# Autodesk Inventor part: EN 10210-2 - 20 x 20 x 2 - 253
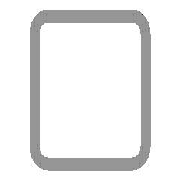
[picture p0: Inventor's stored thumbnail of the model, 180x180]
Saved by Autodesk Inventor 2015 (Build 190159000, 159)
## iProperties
Created: 2014-02
Part Number: EN 10210-2 - 20 x 20 x 2 - 253
Material: Steel, Mild
Description: Tube
Document SubType Name: Modeling
Standard: DIN
Designer: TREINA6
Standard Revision: 1997
Standards Organization: DIN
Language: en-US
Size Designation: 20 x 20 x 2
Categories: <MemberInstance><Categories><Category DisplayName="Structural Shapes" InternalName="089c4875-fa83-4c05-b084-43b9cc11f5ed" Mnemonic="GRDR"><CategoryParameter Dis
Stock Number: 20 x 20 x 2
Density: 7.85 g/cm^3
Appearance: Semi-Polished
_CCFamilyMember: 1
_CCFamilyDisplayName: DIN EN 10210-2 (Square) - Tube
_FrameMemberDoc: Frame Member File
_Version: 15.0.0
_GetPNFromCC: 1
IsCustomPart: 1
Author: TREINA6
G_L: 253,000 mm
G_W: 20,000 mm
G_H: 20,000 mm
+92CAF834-4A3A-427E-AD43-0E28CC12F767+CUTDETAIL1: Miter 45,00 deg
+C6974BCF-1B59-4DE7-8265-DB1344D5870A+CUTDETAIL2: Miter 45,00 deg
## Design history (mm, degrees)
node "Start plane"
node "End plane"
sketch "Sketch"
  geometry: L1 (-10, -7)-(-10, 7); L2 (-7, 10)-(7, 10); L3 (10, 7)-(10, -7); L4 (7, -10)-(-7, -10); L5 (-7, 8)-(7, 8); L6 (8, 7)-(8, -7); L7 (7, -8)-(-7, -8); L8 (-8, -7)-(-8, 7); L9 (0, 14.87)-(0, -14.87) reference; L10 (-14.87, 0)-(14.87, 0) reference; A1 r 3 centre (-7, -7) between (-10, -7) and (-7, -10); A2 r 3 centre (-7, 7) between (-7, 10) and (-10, 7); A3 r 3 centre (7, 7) between (10, 7) and (7, 10); A4 r 3 centre (7, -7) between (7, -10) and (10, -7); A5 r 1 centre (-7, 7) between (-7, 8) and (-8, 7); A6 r 1 centre (7, 7) between (8, 7) and (7, 8); A7 r 1 centre (7, -7) between (7, -8) and (8, -7); A8 r 1 centre (-7, -7) between (-8, -7) and (-7, -8)
  constraints: 16 end point, 16 point on circle, 8 centre point, 8 tangent, 4 parallel, 3 equal radius, 2 perpendicular, 7 other
  dimensions: "d7" = 3 radius of A1 (= G_IR); "d10" = 20 distance between parallel lines of L2 L4 (= G_H); "d11" = 20 distance between parallel lines of L1 L3 (= G_W); "d12" = 2 distance between parallel lines of L3 L6 (= G_T); "d15" = 10 distance between parallel lines of L2 L10 (= 0.5 x d10); "d16" = 10 distance between parallel lines of L9 L3 (= 0.5 x d11)
extrude "Body" new body sketch "Sketch" stored distance "d3" = 253 (= G_L); taper "d4" = 0 deg
node "Driven Length"
  sketch "Sketch3"
    geometry: L1 (0, 0)-(10, 0) reference
    constraints: 2 end point, 1 horizontal
  workplane "Work Plane3"
  sketch "Sketch4"
    geometry: L1 (-2, 0)-(12, 0) reference; L2 (-2, 253)-(12, 253) reference
    dimensions: "d18" = 253 distance between parallel lines of L1 L2 (derived)
workplane "Work Plane4"
split "Split1"
workplane "Work Plane5"
split "Split2"
body "Solid1"
other parameters: "G_W" = 20 [user parameter; used in 1 equation term], "G_H" = 20 [user parameter; used in 1 equation term], "G_T" = 2 [user parameter; used in 1 equation term], "G_IR" = 3 [user parameter; used in 1 equation term], "G_L" = 253 (= d18) [user parameter; used in 1 equation term], "G_OFFSET_START" = 0 [user parameter; used in 1 equation term], "G_OFFSET_END" = 0 [user parameter; used in 1 equation term], "d13" = 0 (computed from G_OFFSET_START), "d14" = 253 (= G_OFFSET_END + B_L), "B_L" = 253 [user parameter; used in 1 equation term], "d17" = 90 deg
